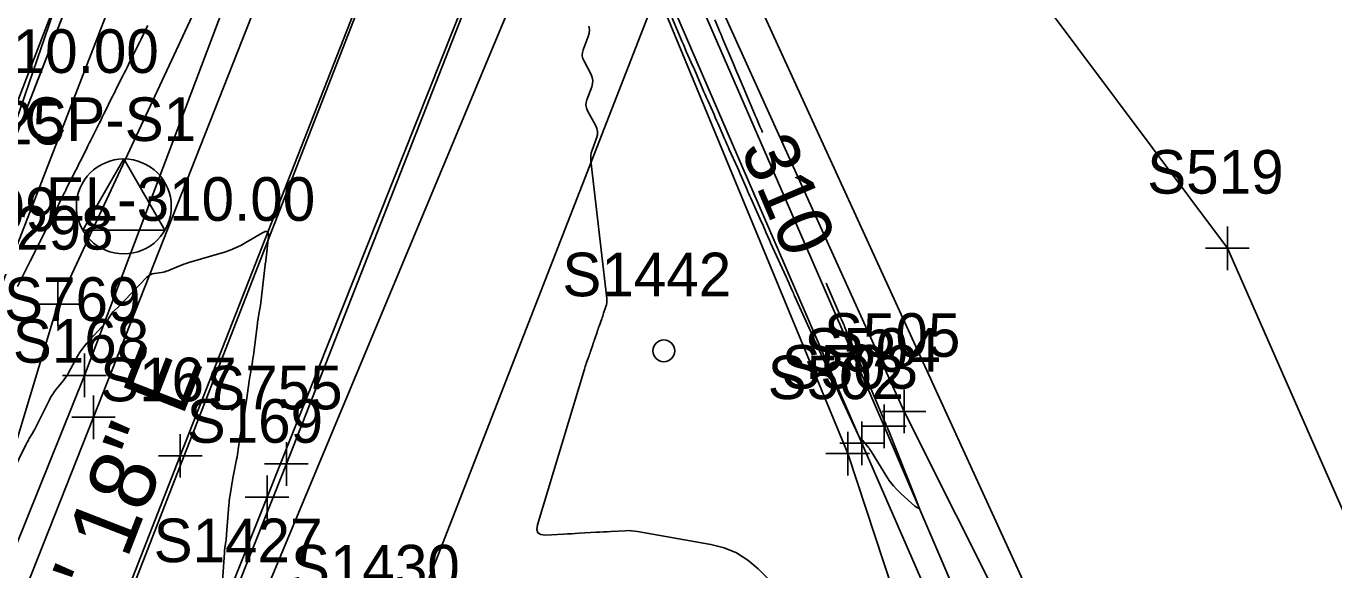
# Model space of a CAD drawing. Extents: x 816928 to 825690, y 436959 to 448212.
# Drawn here: x 818798.2 to 818918.1, y 444837.4 to 444887.3 of the extents above; entities that cross this region are included whole.
import ezdxf

# ---------------------------------------------------------------- set-up
doc = ezdxf.new("R2010")
doc.units = 0
for name, color, linetype in [('SURVEY - CENTERLINE - Preliminary', 7, 'Continuous'), ('SURVEY - CENTERLINE - Preliminary Text', 7, 'Continuous'), ('SURVEY - CONTOURS - Index with Text', 7, 'Continuous'), ('SURVEY - CONTOURS - Intermediate with optional Text', 7, 'Continuous'), ('SURVEY - CONTROL with Text', 7, 'Continuous'), ('SURVEY - DRAINAGE - Area Shapes', 7, 'Continuous'), ('SURVEY - DTM - Breaklines', 7, 'Continuous'), ('SURVEY - DTM - Breaklines - Points - Locators', 7, 'Continuous'), ('SURVEY - DTM - Breaklines - Points - Numbers', 7, 'Continuous'), ('SURVEY - DTM - Spot Points - Locators', 7, 'Continuous'), ('SURVEY - DTM - Spot Points - Point Numbers', 7, 'Continuous'), ('SURVEY - NON-TRANSPORTATION - Features', 7, 'Continuous'), ('SURVEY - PROPERTY - Parcels', 7, 'Continuous'), ('SURVEY - PROPERTY - Property Lines - Points - Elevations', 7, 'Continuous'), ('SURVEY - PROPERTY - Property Lines - Points - Numbers', 7, 'Continuous'), ('SURVEY - PROPERTY - ROW Lines', 7, 'Continuous'), ('SURVEY - TRANSPORTATION - Roads', 7, 'Continuous'), ('SURVEY - TRANSPORTATION - Roads - Points - Locators', 7, 'Continuous'), ('SURVEY - TRANSPORTATION - Roads - Points - Numbers', 7, 'Continuous'), ('SURVEY - UTILITIES - Gas - Points - Locators', 7, 'Continuous'), ('SURVEY - UTILITIES - Gas - Points - Numbers', 7, 'Continuous'), ('SURVEY - UTILITIES - Gas with Text', 7, 'Continuous'), ('SURVEY - UTILITIES - Water - Points - Locators', 7, 'Continuous'), ('SURVEY - UTILITIES - Water - Points - Numbers', 7, 'Continuous'), ('SURVEY - UTILITIES - Water with Text', 7, 'Continuous'), ('SURVEY - VEGETATION - Features - Points - Locators', 7, 'Continuous'), ('SURVEY - VEGETATION - Features - Points - Numbers', 7, 'Continuous'), ('SURVEY - VEGETATION - Features with Text', 7, 'Continuous')]:
    doc.layers.add(name, color=color, linetype=linetype)

msp = doc.modelspace()

# ---------------------------------------------------------------- linework, layer by layer
at = {"layer": 'SURVEY - CENTERLINE - Preliminary'}
msp.add_line((818740.59, 444662.66), (818873.38, 445003.74), dxfattribs=at)
at = {"layer": 'SURVEY - CONTOURS - Index with Text'}
for points in [[(818857.43, 444888.03), (818858.19, 444886.23), (818858.32, 444885.92), (818858.46, 444885.61), (818858.59, 444885.3), (818858.73, 444884.99), (818859.19, 444883.97), (818859.28, 444883.76), (818859.38, 444883.54), (818859.47, 444883.32), (818859.57, 444883.1), (818860.18, 444881.65), (818860.31, 444881.34), (818860.45, 444881.04), (818860.58, 444880.73), (818860.72, 444880.42), (818861.28, 444879.19), (818861.39, 444878.92), (818861.51, 444878.66), (818861.63, 444878.39), (818861.74, 444878.13), (818862.24, 444876.97), (818862.34, 444876.72), (818862.45, 444876.47), (818862.56, 444876.22), (818862.67, 444875.98), (818863.42, 444874.33), (818863.54, 444874.05), (818863.66, 444873.77), (818863.78, 444873.49), (818863.9, 444873.21), (818864.3, 444872.3), (818864.38, 444872.1), (818864.47, 444871.91), (818864.55, 444871.71), (818864.64, 444871.52), (818865.63, 444869.33), (818865.74, 444869.1), (818865.84, 444868.87), (818865.94, 444868.65), (818866.03, 444868.42), (818866.35, 444867.67), (818866.42, 444867.51), (818866.49, 444867.35), (818866.56, 444867.2), (818866.64, 444867.04), (818867.88, 444864.31), (818867.96, 444864.14), (818868.03, 444863.96), (818868.11, 444863.79), (818868.18, 444863.62), (818868.43, 444863.05), (818868.48, 444862.93), (818868.54, 444862.81), (818868.59, 444862.69), (818868.64, 444862.57), (818870.15, 444859.28), (818870.2, 444859.16), (818870.25, 444859.04), (818870.31, 444858.93), (818870.36, 444858.81), (818870.52, 444858.43), (818870.56, 444858.35), (818870.59, 444858.27), (818870.63, 444858.19), (818870.67, 444858.11), (818872.45, 444854.22), (818872.48, 444854.17), (818872.5, 444854.11), (818872.53, 444854.06), (818872.55, 444854), (818872.63, 444853.81), (818872.65, 444853.77), (818872.67, 444853.74), (818872.69, 444853.7), (818872.7, 444853.66), (818874.48, 444849.83), (818874.51, 444849.76), (818874.55, 444849.7), (818874.59, 444849.64), (818874.64, 444849.59), (818874.86, 444849.35), (818874.87, 444849.34), (818874.87, 444849.34), (818874.87, 444849.33), (818874.88, 444849.33), (818874.89, 444849.31), (818874.89, 444849.31), (818874.89, 444849.3), (818874.9, 444849.3), (818874.9, 444849.3), (818874.96, 444849.23), (818874.98, 444849.21), (818874.99, 444849.2), (818875, 444849.18), (818875.02, 444849.16), (818875.4, 444848.69), (818875.48, 444848.59), (818875.56, 444848.48), (818875.64, 444848.37), (818875.71, 444848.26), (818877.1, 444845.99), (818877.38, 444845.56), (818877.7, 444845.15), (818878.04, 444844.77), (818878.41, 444844.42), (818879.67, 444843.29), (818879.9, 444843.12), (818880.01, 444843.09), (818880.03, 444843.21), (818879.95, 444843.48), (818879.01, 444845.87), (818879, 444845.89), (818878.99, 444845.92), (818878.98, 444845.94), (818878.97, 444845.96), (818878.93, 444846.04), (818878.92, 444846.06), (818878.92, 444846.07), (818878.91, 444846.09), (818878.9, 444846.1), (818877.25, 444850.24), (818877.23, 444850.3), (818877.21, 444850.36), (818877.18, 444850.41), (818877.15, 444850.47), (818877.07, 444850.65), (818877.05, 444850.69), (818877.03, 444850.73), (818877.01, 444850.77), (818877, 444850.81), (818876.81, 444851.26), (818876.81, 444851.27), (818876.81, 444851.27), (818876.8, 444851.27), (818876.8, 444851.28), (818876.79, 444851.29), (818876.79, 444851.3), (818876.79, 444851.3), (818876.79, 444851.3), (818876.79, 444851.31), (818875.14, 444855.23), (818875.11, 444855.31), (818875.07, 444855.39), (818875.04, 444855.47), (818875.01, 444855.55), (818874.9, 444855.81), (818874.87, 444855.86), (818874.85, 444855.92), (818874.83, 444855.97), (818874.8, 444856.03), (818873.27, 444859.67), (818873.23, 444859.77), (818873.19, 444859.87), (818873.14, 444859.97), (818873.1, 444860.07), (818872.96, 444860.39), (818872.93, 444860.46), (818872.9, 444860.53), (818872.87, 444860.6), (818872.85, 444860.67), (818871.56, 444863.72)], [(818865.72, 444877.54), (818865.65, 444877.72), (818865.56, 444877.91), (818865.48, 444878.1), (818865.22, 444878.72), (818865.16, 444878.85), (818865.1, 444878.99), (818865.05, 444879.12), (818864.99, 444879.25), (818863.95, 444881.73), (818863.85, 444881.95), (818863.76, 444882.16), (818863.67, 444882.38), (818863.58, 444882.59), (818863.28, 444883.3), (818863.21, 444883.45), (818863.15, 444883.6), (818863.08, 444883.75), (818863.02, 444883.9), (818862.09, 444886.11), (818861.99, 444886.35), (818861.88, 444886.59), (818861.78, 444886.84), (818861.67, 444887.08), (818861.33, 444887.87)]]:
    msp.add_lwpolyline(points, dxfattribs=at)
at = {"layer": 'SURVEY - CONTOURS - Intermediate with optional Text'}
for points in [[(818797.45, 444863.43), (818798.63, 444865.76), (818798.74, 444865.97), (818798.84, 444866.18), (818798.95, 444866.39), (818799.05, 444866.6), (818799.39, 444867.29), (818799.46, 444867.44), (818799.54, 444867.59), (818799.61, 444867.73), (818799.68, 444867.88), (818800.71, 444869.91), (818800.83, 444870.16), (818800.96, 444870.41), (818801.08, 444870.66), (818801.21, 444870.91), (818801.61, 444871.73), (818801.7, 444871.91), (818801.79, 444872.08), (818801.88, 444872.26), (818801.96, 444872.44), (818802.8, 444874.09), (818802.94, 444874.38), (818803.09, 444874.67), (818803.23, 444874.95), (818803.37, 444875.24), (818803.83, 444876.18), (818803.93, 444876.38), (818804.03, 444876.58), (818804.13, 444876.78), (818804.24, 444876.98), (818804.93, 444878.36), (818805.08, 444878.66), (818805.22, 444878.95), (818805.37, 444879.25), (818805.52, 444879.54), (818806.05, 444880.62), (818806.16, 444880.85), (818806.27, 444881.08), (818806.39, 444881.31), (818806.5, 444881.54), (818807.11, 444882.74), (818807.24, 444883), (818807.37, 444883.26), (818807.49, 444883.52), (818807.62, 444883.77), (818808.24, 444885.04), (818808.38, 444885.31), (818808.51, 444885.58), (818808.65, 444885.85), (818808.78, 444886.12), (818809.29, 444887.14), (818809.4, 444887.36)], [(818849.8, 444887.31), (818849.85, 444886.99), (818849.83, 444886.66), (818849.74, 444886.34), (818849.28, 444885.14), (818849.21, 444884.88), (818849.19, 444884.63), (818849.23, 444884.38), (818849.33, 444884.14), (818850, 444882.87), (818850.11, 444882.59), (818850.16, 444882.31), (818850.14, 444882.03), (818850.07, 444881.75), (818849.62, 444880.55), (818849.55, 444880.29), (818849.54, 444880.04), (818849.58, 444879.8), (818849.69, 444879.55), (818850.42, 444878.22), (818850.54, 444877.93), (818850.6, 444877.63), (818850.59, 444877.33), (818850.51, 444877.03), (818850.1, 444875.92), (818850.03, 444875.68), (818849.98, 444875.44), (818849.97, 444875.19), (818849.98, 444874.94), (818851.45, 444862.33), (818851.46, 444862.14), (818851.45, 444861.95), (818851.42, 444861.76), (818851.36, 444861.58), (818851.16, 444860.97), (818851.11, 444860.85), (818851.07, 444860.72), (818851.02, 444860.59), (818850.98, 444860.46), (818850.75, 444859.8), (818850.7, 444859.66), (818850.66, 444859.52), (818850.61, 444859.38), (818850.56, 444859.24), (818850.35, 444858.62), (818850.3, 444858.48), (818850.25, 444858.35), (818850.21, 444858.22), (818850.16, 444858.08), (818849.95, 444857.47), (818849.91, 444857.34), (818849.86, 444857.21), (818849.82, 444857.08), (818849.77, 444856.95), (818849.57, 444856.36), (818849.52, 444856.23), (818849.48, 444856.1), (818849.44, 444855.97), (818849.4, 444855.84), (818845.1, 444841.56), (818845.04, 444841.14), (818845.14, 444840.84), (818845.4, 444840.68), (818845.83, 444840.64), (818847.49, 444840.73), (818847.85, 444840.75), (818848.2, 444840.76), (818848.56, 444840.78), (818848.91, 444840.8), (818850.47, 444840.89), (818850.81, 444840.9), (818851.14, 444840.92), (818851.47, 444840.94), (818851.81, 444840.96), (818853.14, 444841.03), (818853.42, 444841.04), (818853.71, 444841.03), (818853.99, 444841), (818854.27, 444840.96), (818860.99, 444839.78), (818862.21, 444839.48), (818863.34, 444839), (818864.38, 444838.35), (818865.33, 444837.54), (818869.35, 444833.53)], [(818796.37, 444845.09), (818798.26, 444848.97), (818798.32, 444849.1), (818798.39, 444849.23), (818798.47, 444849.37), (818798.54, 444849.49), (818798.8, 444849.91), (818798.85, 444850), (818798.9, 444850.1), (818798.95, 444850.19), (818799, 444850.28), (818800.38, 444853.03), (818800.52, 444853.3), (818800.68, 444853.56), (818800.85, 444853.81), (818801.04, 444854.05), (818801.66, 444854.82), (818801.79, 444854.99), (818801.92, 444855.16), (818802.03, 444855.34), (818802.14, 444855.52), (818802.96, 444857.03), (818803.14, 444857.35), (818803.34, 444857.65), (818803.56, 444857.94), (818803.8, 444858.22), (818805.48, 444860.06), (818805.57, 444860.16), (818805.65, 444860.26), (818805.72, 444860.37), (818805.79, 444860.48), (818806.01, 444860.84), (818806.06, 444860.92), (818806.12, 444860.99), (818806.17, 444861.06), (818806.24, 444861.13), (818806.79, 444861.66), (818806.91, 444861.78), (818807.03, 444861.89), (818807.14, 444862.01), (818807.26, 444862.13), (818809.3, 444864.27), (818809.45, 444864.4), (818809.62, 444864.51), (818809.8, 444864.58), (818810, 444864.62), (818810.66, 444864.72), (818810.81, 444864.74), (818810.95, 444864.78), (818811.08, 444864.82), (818811.22, 444864.87), (818812.25, 444865.3), (818812.47, 444865.39), (818812.69, 444865.47), (818812.92, 444865.55), (818813.15, 444865.62), (818816.42, 444866.59), (818816.93, 444866.76), (818817.42, 444866.96), (818817.91, 444867.19), (818818.38, 444867.45), (818819.89, 444868.36), (818820.16, 444868.48), (818820.35, 444868.47), (818820.45, 444868.3), (818820.45, 444868), (818820.24, 444866.05), (818820.23, 444865.99), (818820.22, 444865.92), (818820.22, 444865.86), (818820.2, 444865.79), (818820.17, 444865.58), (818820.16, 444865.54), (818820.15, 444865.49), (818820.15, 444865.45), (818820.14, 444865.4), (818819.71, 444861.7), (818819.69, 444861.54), (818819.67, 444861.38), (818819.64, 444861.22), (818819.61, 444861.05), (818819.52, 444860.52), (818819.5, 444860.41), (818819.48, 444860.3), (818819.46, 444860.18), (818819.45, 444860.07), (818819.11, 444857.34), (818819.07, 444857.09), (818819.03, 444856.83), (818818.99, 444856.58), (818818.95, 444856.32), (818818.79, 444855.49), (818818.76, 444855.31), (818818.73, 444855.14), (818818.7, 444854.96), (818818.67, 444854.78), (818818.43, 444852.96), (818818.38, 444852.62), (818818.33, 444852.28), (818818.27, 444851.94), (818818.21, 444851.6), (818817.99, 444850.48), (818817.95, 444850.25), (818817.91, 444850.01), (818817.87, 444849.77), (818817.83, 444849.53), (818817.68, 444848.47), (818817.65, 444848.24), (818817.61, 444848.02), (818817.57, 444847.79), (818817.53, 444847.57), (818817.25, 444846.16), (818817.2, 444845.89), (818817.15, 444845.62), (818817.1, 444845.34), (818817.05, 444845.07), (818816.91, 444844.18), (818816.88, 444843.99), (818816.86, 444843.79), (818816.84, 444843.6), (818816.82, 444843.41), (818816.61, 444840.68), (818816.6, 444840.52), (818816.58, 444840.35), (818816.56, 444840.19), (818816.54, 444840.03), (818816.46, 444839.5), (818816.44, 444839.39), (818816.43, 444839.27), (818816.42, 444839.16), (818816.41, 444839.04), (818816.15, 444835.11)]]:
    msp.add_lwpolyline(points, dxfattribs=at)
at = {"layer": 'SURVEY - CONTROL with Text'}
for p, q in [((818807.2, 444875.12), (818803.43, 444868.6)), ((818810.96, 444868.6), (818807.2, 444875.12)), ((818807.2, 444870.77), (818807.2, 444870.77)), ((818803.43, 444868.6), (818810.96, 444868.6))]:
    msp.add_line(p, q, dxfattribs=at)
msp.add_circle((818807.2, 444870.77), 4.35, dxfattribs=at)
at = {"layer": 'SURVEY - DRAINAGE - Area Shapes'}
msp.add_line((818740.59, 444662.66), (818873.38, 445003.74), dxfattribs=at)
at = {"layer": 'SURVEY - DTM - Breaklines'}
for points in [[(818668.59, 444528.25), (818685.72, 444574.97), (818701.79, 444621.45), (818719.06, 444668.19), (818736.24, 444715.25), (818753.95, 444762.85), (818774.46, 444810.97), (818792.45, 444864.45), (818805.63, 444902.92), (818824.67, 444952.98), (818842.7, 444999.99), (818860.04, 445043.66), (818874.78, 445092.7), (818880.83, 445100.46), (818882.71, 445127.32), (818888.7, 445139.72), (818911.77, 445177.18)], [(818674.6, 444526.59), (818691.48, 444572.45), (818707.88, 444620.16), (818723.91, 444667.23), (818740.64, 444713.78), (818759.18, 444760.75), (818780.01, 444808.95), (818796, 444863.51), (818810.8, 444901.84), (818829.91, 444950.6), (818849.2, 444995.99), (818867.15, 445042.08), (818885.66, 445087.7), (818887.91, 445097.82), (818891.19, 445123.69), (818896.18, 445136.06), (818917.38, 445175.79)], [(818676.31, 444526.27), (818695.98, 444570.72), (818712.39, 444618.98), (818728.83, 444665.29), (818745.89, 444712.28), (818764.81, 444759.05), (818784.52, 444806.67), (818801.14, 444861.81), (818818.98, 444900.09), (818838.24, 444946.22), (818855.87, 444992.17), (818873.7, 445038.58), (818892.29, 445085.58), (818894.59, 445096.56), (818896.48, 445123.31), (818901.19, 445133.75), (818919.53, 445174.23), (818947.17, 445168.06)], [(818958.14, 445160.07), (818932.68, 445121.49), (818907.76, 445078.47), (818886.28, 445033.29), (818867.24, 444986.88), (818848.65, 444941.09), (818830.33, 444893.79), (818812.37, 444847.9), (818794.09, 444801.19), (818775.41, 444755.12), (818757.32, 444708.61), (818740.17, 444661.6), (818740.23, 444661.38), (818723.38, 444614.36), (818707.23, 444567.59), (818689.2, 444521.03)], [(818819.22, 444833.15), (818842.75, 444889.53), (818852.46, 444901.01)], [(818857.91, 444897.86), (818878.69, 444851.98), (818893.01, 444823.39), (818907, 444770.76), (818925.4, 444721.82), (818926.27, 444701.98)], [(818856.71, 444897.06), (818876.87, 444850.61), (818889.63, 444820.8), (818906.51, 444770.26), (818923.86, 444720.86), (818923.7, 444700.72)], [(818854.93, 444895.1), (818874.81, 444849.06), (818887.81, 444819.2), (818904.67, 444769.55), (818922.2, 444718.81), (818921.87, 444700.22)], [(818854.32, 444894.62), (818873.53, 444848.1), (818884.27, 444815.43), (818904, 444768.52), (818920.08, 444715.19), (818920.25, 444699.97)]]:
    msp.add_lwpolyline(points, dxfattribs=at)
at = {"layer": 'SURVEY - DTM - Breaklines - Points - Locators'}
for p, q in [((818801.14, 444863.81), (818801.14, 444859.81)), ((818803.14, 444861.81), (818799.14, 444861.81)), ((818878.69, 444853.98), (818878.69, 444849.98)), ((818880.69, 444851.98), (818876.69, 444851.98)), ((818876.87, 444852.61), (818876.87, 444848.61)), ((818874.81, 444851.06), (818874.81, 444847.06)), ((818812.37, 444849.9), (818812.37, 444845.9)), ((818873.53, 444850.1), (818873.53, 444846.1)), ((818878.87, 444850.61), (818874.87, 444850.61)), ((818876.81, 444849.06), (818872.81, 444849.06)), ((818814.37, 444847.9), (818810.37, 444847.9)), ((818875.53, 444848.1), (818871.53, 444848.1))]:
    msp.add_line(p, q, dxfattribs=at)
at = {"layer": 'SURVEY - DTM - Spot Points - Locators'}
msp.add_circle((818856.67, 444857.53), 1, dxfattribs=at)
at = {"layer": 'SURVEY - NON-TRANSPORTATION - Features'}
for points in [[(818640.15, 444520.89), (818666.05, 444525.13), (818695.51, 444604.3), (818745.61, 444742.32), (818768.23, 444804.49), (818806.14, 444902.96), (818848.51, 445015.37), (818878.72, 445102.03)], [(818920.17, 445009.4), (818906.24, 444999.97), (818861.1, 444898.73), (818921.08, 444767.65), (818930.54, 444734.6), (818929.8, 444730.51)]]:
    msp.add_lwpolyline(points, dxfattribs=at)
at = {"layer": 'SURVEY - PROPERTY - Parcels'}
for p, q in [((818795.05, 444871.45), (818850.08, 445012.81)), ((818816.41, 444788.51), (818896.67, 444994.67))]:
    msp.add_line(p, q, dxfattribs=at)
at = {"layer": 'SURVEY - PROPERTY - ROW Lines'}
for p, q in [((818717.18, 444671.42), (818850.08, 445012.81)), ((818764.01, 444653.9), (818896.67, 444994.67))]:
    msp.add_line(p, q, dxfattribs=at)
at = {"layer": 'SURVEY - TRANSPORTATION - Roads'}
for points in [[(818965.23, 445155.36), (818951.41, 445165.35), (818926.02, 445127.5), (818900.33, 445082.5), (818878.31, 445036.45), (818858.82, 444990.15), (818840.56, 444944.19), (818822.72, 444897.89), (818804.42, 444851.44), (818785.95, 444804.73), (818767.42, 444758.09), (818749.48, 444712.19), (818731.94, 444664.32), (818715.46, 444617.82), (818698.91, 444570.49), (818680.86, 444523.94)], [(818965.23, 445155.36), (818938.62, 445116.05), (818915.35, 445074.62), (818893.36, 445028.08), (818874.3, 444982.23), (818856.42, 444936.82), (818838.53, 444889.93), (818820.32, 444844.1), (818801.63, 444797.25), (818782.89, 444750.29), (818765.2, 444704.77), (818748.05, 444657.94), (818731.68, 444611.01), (818715.16, 444564.48), (818697.02, 444517.16)], [(818965.23, 445155.36), (818938.62, 445116.05), (818915.35, 445074.62), (818898.78, 445039.54), (818893.36, 445028.08), (818891.24, 445022.96), (818874.3, 444982.23), (818856.42, 444936.82), (818838.53, 444889.93), (818820.32, 444844.1), (818801.63, 444797.25), (818782.89, 444750.29), (818765.2, 444704.77), (818757.63, 444684.09), (818748.68, 444659.65), (818748.05, 444657.94), (818731.68, 444611.01), (818715.16, 444564.48), (818697.02, 444517.16)]]:
    msp.add_lwpolyline(points, dxfattribs=at)
at = {"layer": 'SURVEY - TRANSPORTATION - Roads - Points - Locators'}
for p, q in [((818804.42, 444853.44), (818804.42, 444849.44)), ((818806.42, 444851.44), (818802.42, 444851.44)), ((818820.32, 444846.1), (818820.32, 444842.1)), ((818822.32, 444844.1), (818818.32, 444844.1))]:
    msp.add_line(p, q, dxfattribs=at)
at = {"layer": 'SURVEY - UTILITIES - Gas - Points - Locators'}
for p, q in [((818803.58, 444857.27), (818803.58, 444853.27)), ((818805.58, 444855.27), (818801.58, 444855.27))]:
    msp.add_line(p, q, dxfattribs=at)
at = {"layer": 'SURVEY - UTILITIES - Gas with Text'}
msp.add_lwpolyline([(818677.99, 444524.55), (818704.19, 444595.26), (818729, 444664.07), (818764.63, 444758.42), (818803.58, 444855.27), (818837.4, 444944.84), (818872.36, 445029.49), (818905.91, 445098), (818946.07, 445164.69)], dxfattribs=at)
at = {"layer": 'SURVEY - UTILITIES - Water - Points - Locators'}
for p, q in [((818822.09, 444849.16), (818822.09, 444845.16)), ((818824.09, 444847.16), (818820.09, 444847.16))]:
    msp.add_line(p, q, dxfattribs=at)
at = {"layer": 'SURVEY - UTILITIES - Water with Text'}
msp.add_lwpolyline([(818803.23, 444799.75), (818822.09, 444847.16), (818840.81, 444894.99), (818859.42, 444943.11), (818878.42, 444989.73), (818897.25, 445035.66), (818918.39, 445078.74), (818943.02, 445121.02), (818943.42, 445156.25), (818947.56, 445166.11), (818971.8, 445201.19), (819041.12, 445261.9), (819085.56, 445324.06), (819114.44, 445364.74), (819142.59, 445406.12), (819261.28, 445567.54), (819325.96, 445650.57), (819357.34, 445697.81), (819381.77, 445739.87), (819404.91, 445783)], dxfattribs=at)
at = {"layer": 'SURVEY - VEGETATION - Features - Points - Locators'}
for p, q in [((818908.31, 444868.94), (818908.31, 444864.94)), ((818910.31, 444866.94), (818906.31, 444866.94))]:
    msp.add_line(p, q, dxfattribs=at)
at = {"layer": 'SURVEY - VEGETATION - Features with Text'}
msp.add_lwpolyline([(818877.45, 444908.25), (818908.31, 444866.94), (818942.96, 444788.14), (818956.68, 444741.89)], dxfattribs=at)

# ---------------------------------------------------------------- texts
at = {"layer": 'SURVEY - CENTERLINE - Preliminary Text'}
msp.add_text('N 21%%d 16\' 18" E', height=6, rotation=68.7285, dxfattribs=at).set_placement((818794.75, 444805.66))
at = {"layer": 'SURVEY - CONTOURS - Index with Text'}
msp.add_text('310', height=5, rotation=292.9082, dxfattribs=at).set_placement((818863.64, 444876.05))
at = {"layer": 'SURVEY - CONTROL with Text'}
msp.add_text('CP-S1', height=4, dxfattribs=at).set_placement((818798.07, 444876.77))
at = {"layer": 'SURVEY - DTM - Breaklines - Points - Numbers'}
for s, p in [('S299', (818788.65, 444868.51)), ('S298', (818793.76, 444866.81)), ('S505', (818871.35, 444856.98)), ('S504', (818869.54, 444855.61)), ('S503', (818867.47, 444854.06)), ('S167', (818805.03, 444852.9)), ('S502', (818866.19, 444853.1)), ('S1427', (818809.93, 444838.15)), ('S1430', (818822.51, 444835.74))]:
    msp.add_text(s, height=4, dxfattribs=at).set_placement(p)
at = {"layer": 'SURVEY - DTM - Spot Points - Point Numbers'}
msp.add_text('S1442', height=4, dxfattribs=at).set_placement((818847.38, 444862.53))
at = {"layer": 'SURVEY - PROPERTY - Property Lines - Points - Elevations'}
for p in [(818785.72, 444883.01), (818800.05, 444869.45)]:
    msp.add_text('EL-310.00', height=4, dxfattribs=at).set_placement(p)
at = {"layer": 'SURVEY - PROPERTY - Property Lines - Points - Numbers'}
msp.add_text('SP225', height=4, dxfattribs=at).set_placement((818785.76, 444876.45))
at = {"layer": 'SURVEY - TRANSPORTATION - Roads - Points - Numbers'}
for s, p in [('S168', (818797.03, 444856.44)), ('S169', (818812.96, 444849.1))]:
    msp.add_text(s, height=4, dxfattribs=at).set_placement(p)
at = {"layer": 'SURVEY - UTILITIES - Gas - Points - Numbers'}
msp.add_text('S769', height=4, dxfattribs=at).set_placement((818796.23, 444860.27))
at = {"layer": 'SURVEY - UTILITIES - Water - Points - Numbers'}
msp.add_text('S755', height=4, dxfattribs=at).set_placement((818814.75, 444852.16))
at = {"layer": 'SURVEY - VEGETATION - Features - Points - Numbers'}
msp.add_text('S519', height=4, dxfattribs=at).set_placement((818900.96, 444871.94))

doc.saveas('drawing.dxf')
